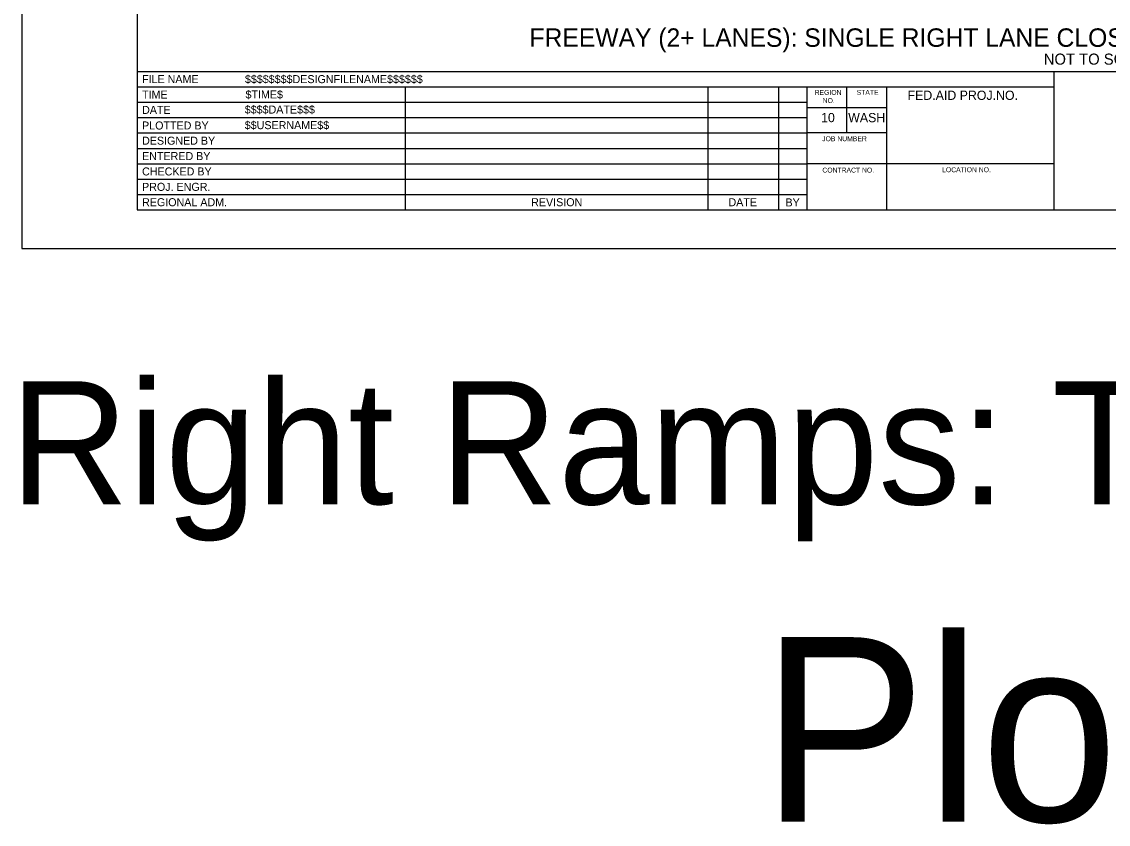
# Model space of a CAD drawing. Extents: x 99999 to 100116, y 99995 to 100013.
# Drawn here: x 100059.06 to 100067.9, y 99995.01 to 100001.53 of the extents above; entities that cross this region are included whole.
import ezdxf

# ---------------------------------------------------------------- set-up
doc = ezdxf.new("R2010")
doc.units = 0
for name, color, linetype in [('SH_DE_DetailHeading1Text', 7, 'Continuous'), ('SH_GI_PlotLimits', 7, 'Continuous'), ('SH_GI_SheetBorder', 7, 'Continuous'), ('SH_GI_SheetLocationText', 7, 'Continuous'), ('SH_GI_SheetTextInCells', 7, 'Continuous'), ('SH_GI_TitleBlockText', 7, 'Continuous')]:
    doc.layers.add(name, color=color, linetype=linetype)

msp = doc.modelspace()

# ---------------------------------------------------------------- linework, layer by layer
at = {"layer": 'SH_GI_PlotLimits'}
msp.add_lwpolyline([(100059.0625, 99999.6875), (100076.0625, 99999.6875), (100076.0625, 100010.6875), (100059.0625, 100010.6875)], close=True, dxfattribs=at)
at = {"layer": 'SH_GI_SheetBorder'}
for p, q in [((100060, 100010.375), (100060, 100000)), ((100060, 100001.1259), (100075.75, 100001.1259)), ((100067.4566, 100000), (100067.4566, 100001.1259)), ((100060, 100001.0008), (100067.4566, 100001.0008)), ((100062.179, 100001.0008), (100062.179, 100000)), ((100064.641, 100001.0008), (100064.641, 100000)), ((100065.2164, 100001.0008), (100065.2164, 100000)), ((100065.4451, 100001.0008), (100065.4451, 100000)), ((100065.7719, 100000.6255), (100065.7719, 100001.0008)), ((100066.0956, 100000), (100066.0956, 100001.0008)), ((100060, 100000.8757), (100062.1821, 100000.8757)), ((100062.1821, 100000.8757), (100065.4466, 100000.8757)), ((100060, 100000.7506), (100062.1821, 100000.7506)), ((100062.1821, 100000.7506), (100065.4466, 100000.7506)), ((100066.0958, 100000.831), (100065.4466, 100000.831)), ((100060, 100000.6255), (100065.4466, 100000.6255)), ((100066.0958, 100000.6255), (100065.4466, 100000.6255)), ((100060, 100000.5004), (100065.4466, 100000.5004)), ((100060, 100000.3753), (100065.4466, 100000.3753)), ((100067.4566, 100000.3753), (100065.4466, 100000.3753)), ((100060, 100000.2502), (100065.4466, 100000.2502)), ((100060, 100000.1251), (100065.4466, 100000.1251)), ((100060, 100000), (100075.75, 100000))]:
    msp.add_line(p, q, dxfattribs=at)

# ---------------------------------------------------------------- texts
at = {"layer": 'SH_DE_DetailHeading1Text'}
for s, height, p in [('FREEWAY (2+ LANES): SINGLE RIGHT LANE CLOSURE (MAINTAIN EXISTING SPEED LIMIT)', 0.15, (100063.191, 100001.3259)), ('NOT TO SCALE', 0.09, (100067.3727, 100001.1809))]:
    msp.add_text(s, height=height, rotation=360, dxfattribs=at).set_placement(p)
at = {"layer": 'SH_GI_SheetLocationText'}
for s, height, p in [('Right Ramps: Tapered On-Ramp', 1, (100058.9666, 99997.6071)), ('Plot 4', 1.5, (100065.0767, 99995.0267))]:
    msp.add_text(s, height=height, dxfattribs=at).set_placement(p)
at = {"layer": 'SH_GI_SheetTextInCells'}
for s, height, p in [('FILE NAME', 0.06505, (100060.041, 100001.0308)), ('TIME', 0.06505, (100060.041, 100000.9057)), ('REGION', 0.04003, (100065.5099, 100000.9352)), ('STATE', 0.04003, (100065.8511, 100000.9357)), ('FED.AID PROJ.NO.', 0.07506, (100066.2652, 100000.8945)), ('DATE', 0.06505, (100060.041, 100000.7806)), ('NO.', 0.04003, (100065.5752, 100000.869)), ('10', 0.07506, (100065.5621, 100000.7131)), ('WASH', 0.07506, (100065.7826, 100000.7131)), ('PLOTTED BY', 0.06505, (100060.041, 100000.6538)), ('DESIGNED BY', 0.065052, (100060.041, 100000.5304)), ('JOB NUMBER', 0.04003, (100065.5712, 100000.5587)), ('ENTERED BY', 0.06505, (100060.041, 100000.4053)), ('CHECKED BY', 0.06505, (100060.041, 100000.2802)), ('CONTRACT NO.', 0.040032, (100065.5725, 100000.3037)), ('LOCATION NO.', 0.040032, (100066.5465, 100000.3067)), ('PROJ. ENGR.', 0.065052, (100060.041, 100000.1551)), ('REGIONAL ADM.', 0.065052, (100060.041, 100000.03)), ('REVISION', 0.06505, (100063.2048, 100000.03)), ('DATE', 0.06505, (100064.8091, 100000.03)), ('BY', 0.06505, (100065.2725, 100000.0285))]:
    msp.add_text(s, height=height, dxfattribs=at).set_placement(p)
at = {"layer": 'SH_GI_TitleBlockText'}
for s, height, p in [('$$$$$$$$DESIGNFILENAME$$$$$$', 0.065052, (100060.8775, 100001.0308)), ('$TIME$', 0.06505, (100060.882, 100000.9059)), ('$$$$DATE$$$', 0.065052, (100060.8759, 100000.7835)), ('$$USERNAME$$', 0.065052, (100060.8759, 100000.6567))]:
    msp.add_text(s, height=height, dxfattribs=at).set_placement(p)

doc.saveas('drawing.dxf')
